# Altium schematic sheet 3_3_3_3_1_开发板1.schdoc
size 762 x 509 mm; Device: Sheet-Symbol; Symbol: Sheet-Symbol; Name: Sheet-Symbol; @Page No: 2; @Page Count: 2; @Schematic Name: 1_1_1_1_3_电源模块; @Project Name: Altium_Altium_Altium_新硬件设计比赛pcb1234567_2025-09-07_2025-09-08_2025-09-08; @Board Name: 1_1_1_1_3_电源模块; @Update Date: 2026-05-23; @Create Time: 14:33:01; @Update Time: 14:01:25; @Page Name: 3_3_3_3_1_开发板1; @Create Date: 2026-05-21
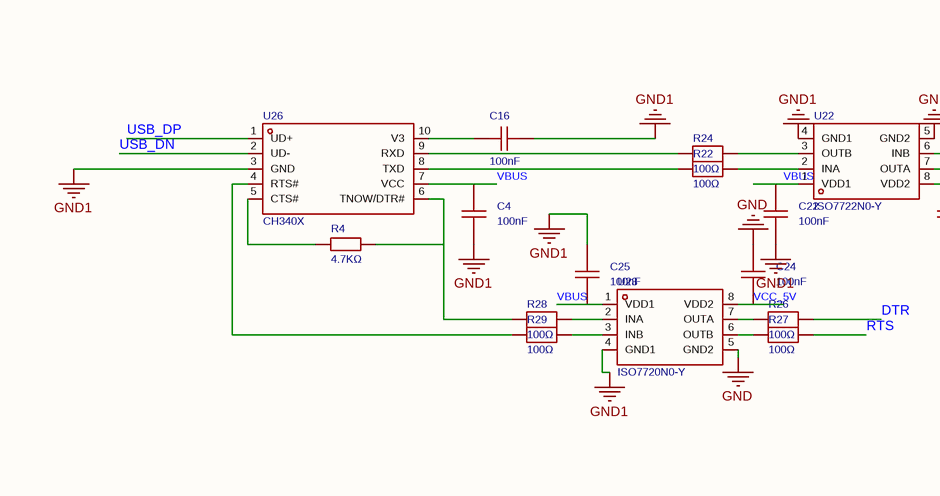
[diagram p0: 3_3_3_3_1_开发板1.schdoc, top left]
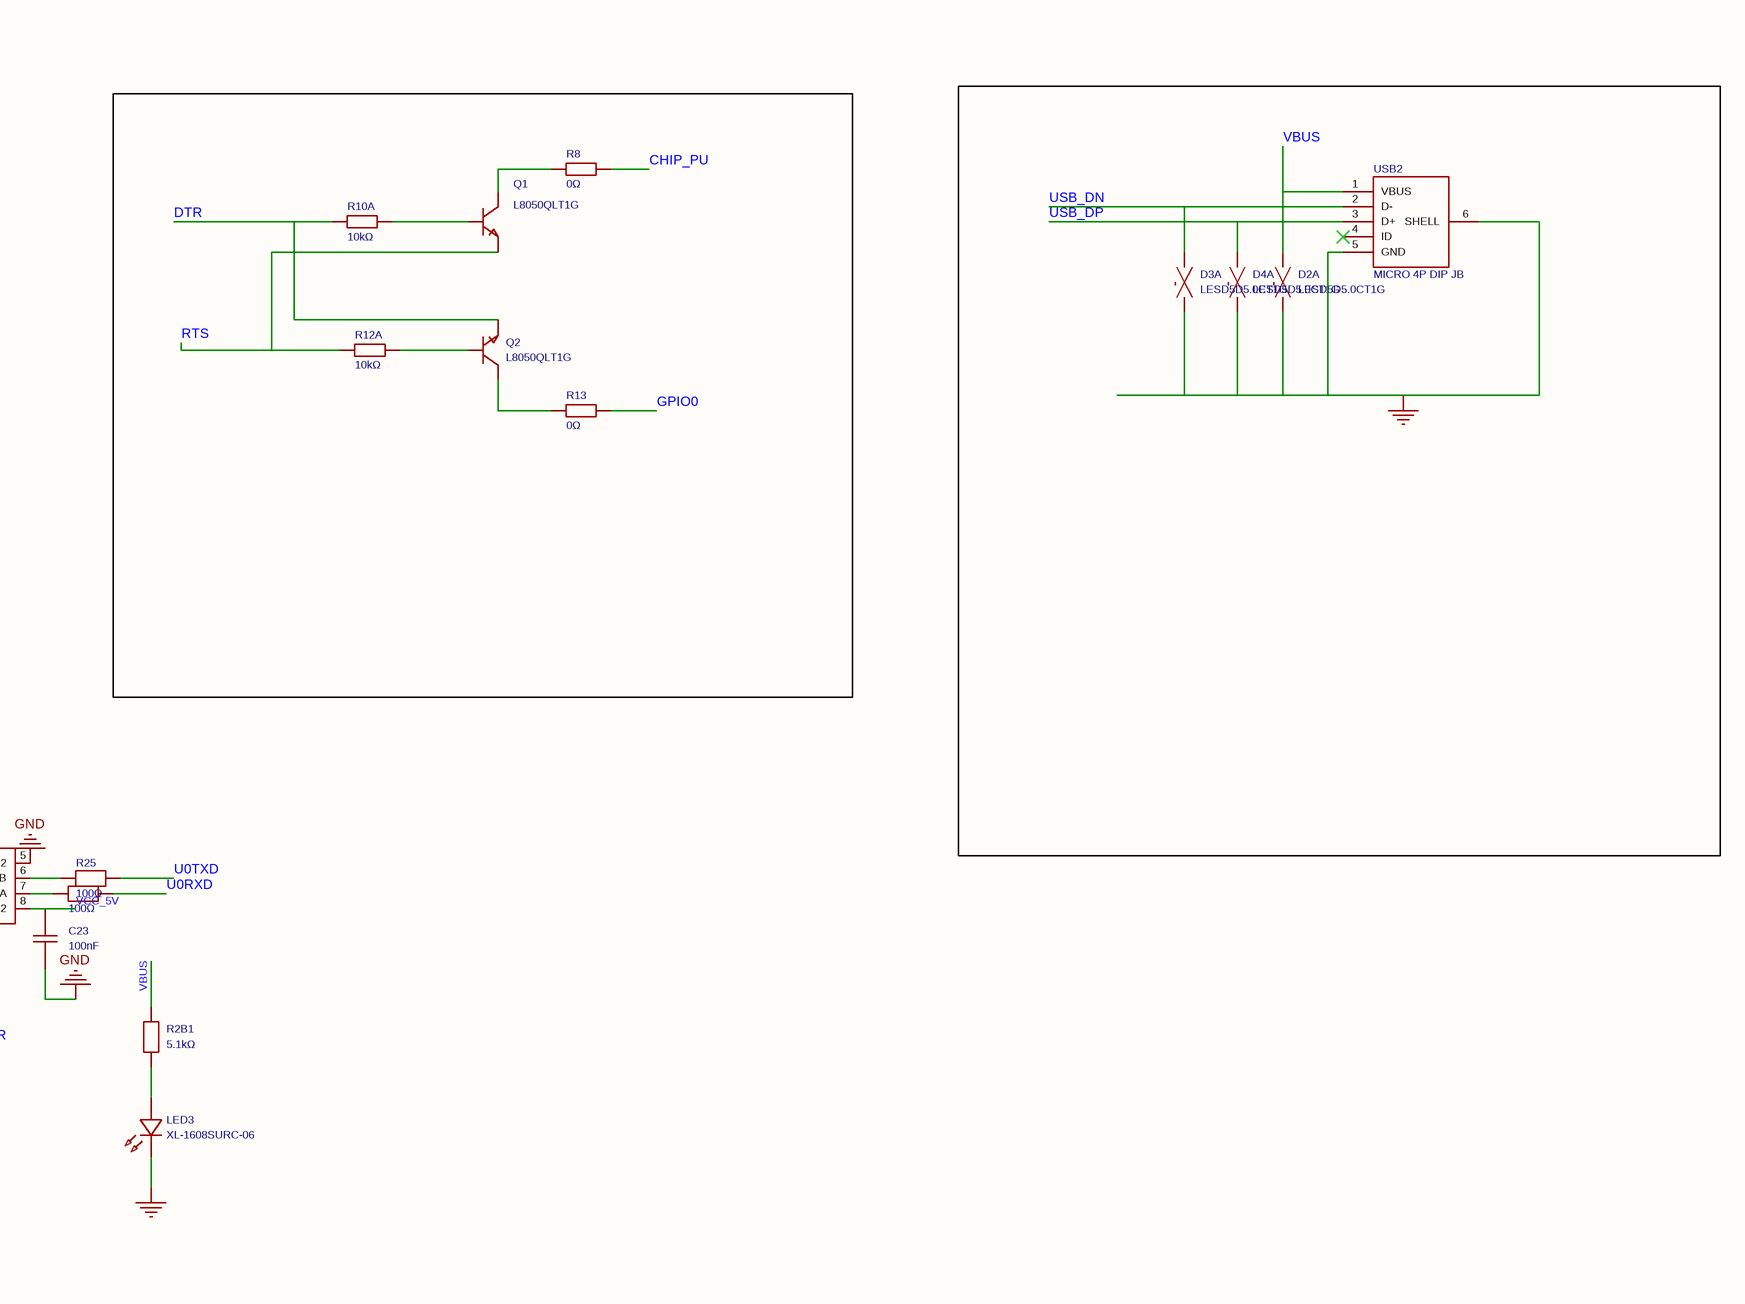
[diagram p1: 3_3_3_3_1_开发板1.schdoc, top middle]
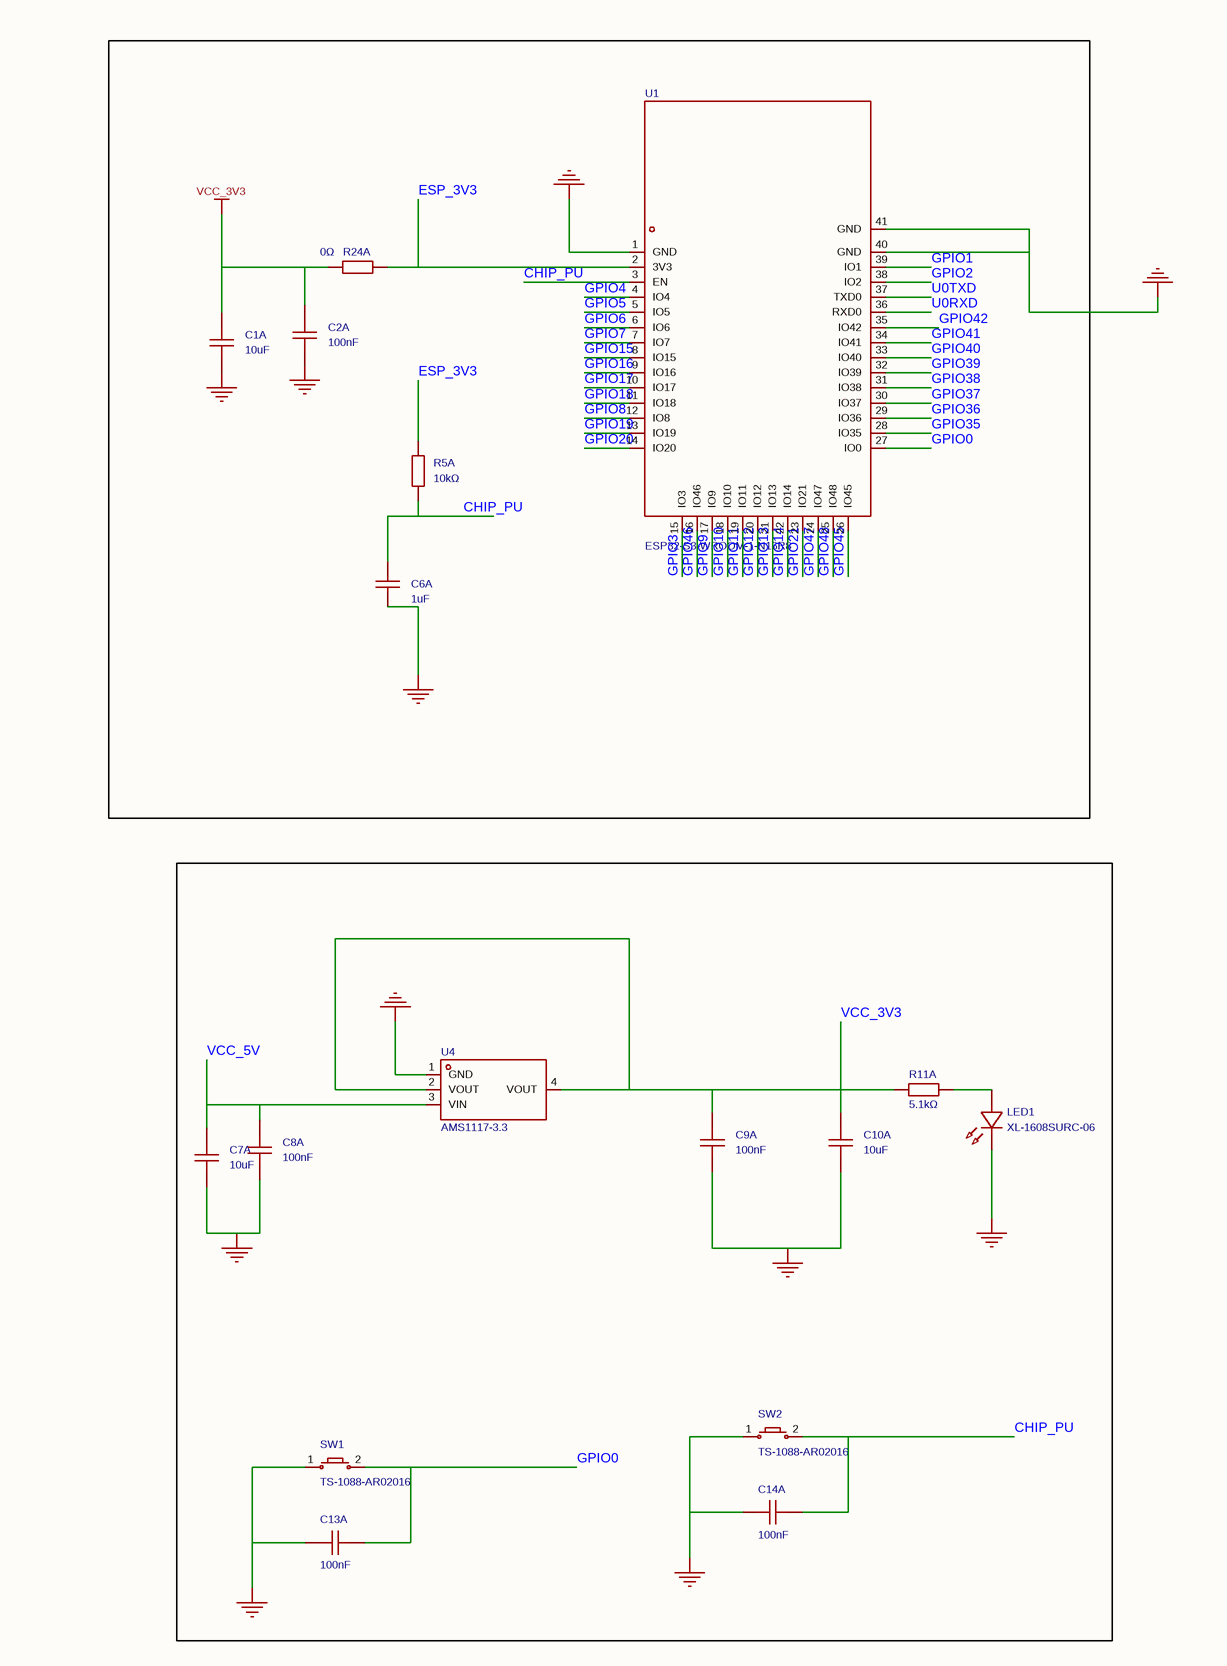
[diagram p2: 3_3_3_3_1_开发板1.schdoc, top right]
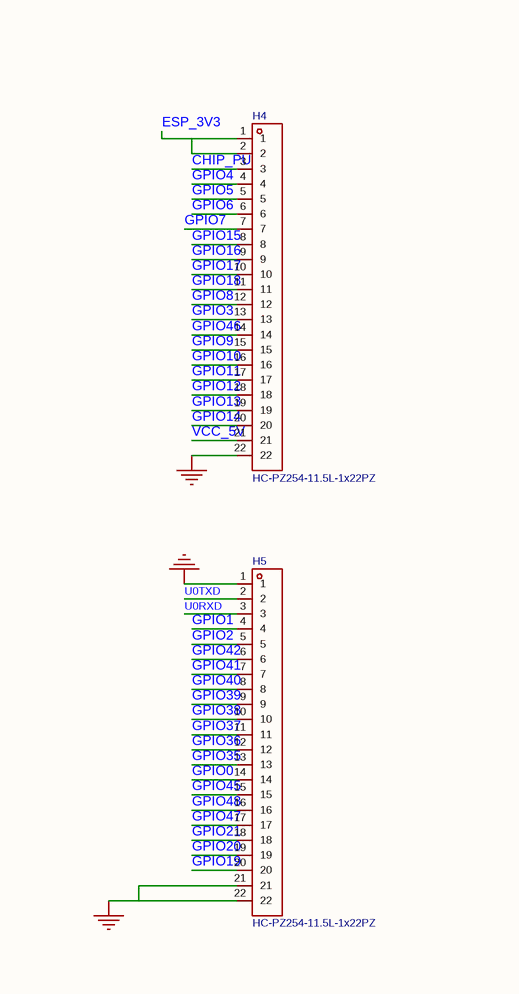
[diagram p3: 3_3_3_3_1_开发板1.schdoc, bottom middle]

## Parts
C1A  10uF  [C0603]
C2A  100nF  [C0603]
C4  100nF  [C0603]
C6A  1uF  [C0603]
C7A  10uF  [C0603]
C8A  100nF  [C0603]
C9A  100nF  [C0603]
C10A  10uF  [C0603]
C13A  100nF  [C0603]
C14A  100nF  [C0603]
C16  100nF  [C0603]
C22  100nF  [C0603]
C23  100nF  [C0603]
C24  100nF  [C0603]
C25  100nF  [C0603]
D2A  LESD5D5.0CT1G  [SOD-523_L1.2-W0.8-LS1.6-BI]
D3A  LESD5D5.0CT1G  [SOD-523_L1.2-W0.8-LS1.6-BI]
D4A  LESD5D5.0CT1G  [SOD-523_L1.2-W0.8-LS1.6-BI]
H4  HC-PZ254-11.5L-1x22PZ  [HDR-TH_22P-P2.54-V-M]
H5  HC-PZ254-11.5L-1x22PZ  [HDR-TH_22P-P2.54-V-M]
LED1  XL-1608SURC-06  [LED0603-RD_RED]
LED3  XL-1608SURC-06  [LED0603-RD_RED]
Q1  L8050QLT1G  [SOT-23-3_L2.9-W1.3-P1.90-LS2.4-BR]
Q2  L8050QLT1G  [SOT-23-3_L2.9-W1.3-P1.90-LS2.4-BR]
R2B1  5.1kΩ  [R0603]
R4  4.7KΩ  [R0603]
R5A  10kΩ  [R0603]
R7A1  100Ω  [R0603]
R8  0Ω  [R0603]
R10A  10kΩ  [R0603]
R11A  5.1kΩ  [R0603]
R12A  10kΩ  [R0603]
R13  0Ω  [R0603]
R22  100Ω  [R0603]
R24  100Ω  [R0603]
R24A  0Ω  [R0603]
R25  100Ω  [R0603]
R26  100Ω  [R0603]
R27  100Ω  [R0603]
R28  100Ω  [R0603]
R29  100Ω  [R0603]
SW1  TS-1088-AR02016  [SW-SMD_L3.9-W3.0-P4.45]
SW2  TS-1088-AR02016  [SW-SMD_L3.9-W3.0-P4.45]
U1  ESP32-S3-WROOM-1-N16R8  [WIRELM-SMD_ESP32-S3-WROOM-1]
U4  AMS1117-3.3  [SOT-223-3_L6.5-W3.4-P2.30-LS7.0-BR]
U22  ISO7722N0-Y  [SOIC-8_L4.9-W3.9-P1.27-LS6.2-BL]
U23  ISO7720N0-Y  [SOIC-8_L4.9-W3.9-P1.27-LS6.2-BL]
U26  CH340X  [MSOP-10_L3.0-W3.0-P0.50-LS5.0-BL]
USB2  MICRO 4P DIP JB  [MICRO-USB-SMD_MICRO-4P-DIP-JB]

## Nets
GND: C1A.1 C2A.1 C6A.1 C7A.1 C8A.1 C9A.1 C10A.1 C13A.1 C14A.1 C23.1 C24.2 H4.22 H5.1 H5.21 H5.22 LED1.1(K) SW1.1 SW2.1 U1.1(GND) U1.40(GND) U1.41(GND) U4.1(GND) U22.5(GND2) U23.5(GND2)
GND1: C4.1 C16.1 C22.1 C25.2 D2A.1 D3A.1 D4A.1 LED3.1(K) U22.4(GND1) U23.4(GND1) U26.3(GND) USB2.5(GND) USB2.6(SHELL)
VCC_3V3: C1A.2 C2A.2 C9A.2 C10A.2 R11A.1 R24A.1 U4.2(VOUT) U4.4(VOUT)
CHIP_PU: C6A.2 C14A.2 H4.3 R5A.1 R8.2 SW2.2 U1.3(EN)
DTR: Q2.2(E) R10A.1 R26.2
ESP_3V3: H4.1 H4.2 R5A.2 R24A.2 U1.2(3V3)
GPIO0: C13A.2 H5.14 R13.2 SW1.2 U1.27(IO0)
GPIO1: H5.4 U1.39(IO1)
GPIO2: H5.5 U1.38(IO2)
GPIO3: H4.13 U1.15(IO3)
GPIO4: H4.4 U1.4(IO4)
GPIO5: H4.5 U1.5(IO5)
GPIO6: H4.6 U1.6(IO6)
GPIO7: H4.7 U1.7(IO7)
GPIO8: H4.12 U1.12(IO8)
GPIO9: H4.15 U1.17(IO9)
GPIO10: H4.16 U1.18(IO10)
GPIO11: H4.17 U1.19(IO11)
GPIO12: H4.18 U1.20(IO12)
GPIO13: H4.19 U1.21(IO13)
GPIO14: H4.20 U1.22(IO14)
GPIO15: H4.8 U1.8(IO15)
GPIO16: H4.9 U1.9(IO16)
GPIO17: H4.10 U1.10(IO17)
GPIO18: H4.11 U1.11(IO18)
GPIO19: H5.20 U1.13(IO19)
GPIO20: H5.19 U1.14(IO20)
GPIO21: H5.18 U1.23(IO21)
GPIO35: H5.13 U1.28(IO35)
GPIO36: H5.12 U1.29(IO36)
GPIO37: H5.11 U1.30(IO37)
GPIO38: H5.10 U1.31(IO38)
GPIO39: H5.9 U1.32(IO39)
GPIO40: H5.8 U1.33(IO40)
GPIO41: H5.7 U1.34(IO41)
GPIO42: H5.6 U1.35(IO42)
GPIO45: H5.15 U1.26(IO45)
GPIO46: H4.14 U1.16(IO46)
GPIO47: H5.17 U1.24(IO47)
GPIO48: H5.16 U1.25(IO48)
RTS: Q1.2(E) R12A.1 R27.2
U0RXD: H5.3 R7A1.2 U1.36(RXD0)
U0TXD: H5.2 R25.2 U1.37(TXD0)
USB_DN: D3A.2 U26.2(UD-) USB2.2(D-)
USB_DP: D4A.2 U26.1(UD+) USB2.3(D+)
VBUS: C4.2 C22.2 C25.1 D2A.2 R2B1.2 U22.1(VDD1) U23.1(VDD1) U26.7(VCC) USB2.1(VBUS)
VCC_5V: C7A.2 C8A.2 C23.2 C24.1 H4.21 U4.3(VIN) U22.8(VDD2) U23.8(VDD2)
NetC16_2: C16.2 U26.10(V3)
NetLED1_2: LED1.2(A) R11A.2
NetLED3_2: LED3.2(A) R2B1.1
NetQ1_1: Q1.1(B) R10A.2
NetQ1_3: Q1.3(C) R8.1
NetQ2_1: Q2.1(B) R12A.2
NetQ2_3: Q2.3(C) R13.1
NetR4_1: R4.1 U26.5(CTS#)
NetR4_2: R4.2 R28.1 U26.6(TNOW/DTR#)
NetR7A1_1: R7A1.1 U22.7(OUTA)
NetR22_1: R22.1 U26.8(TXD)
NetR22_2: R22.2 U22.2(INA)
NetR24_1: R24.1 U26.9(RXD)
NetR24_2: R24.2 U22.3(OUTB)
NetR25_1: R25.1 U22.6(INB)
NetR26_1: R26.1 U23.7(OUTA)
NetR27_1: R27.1 U23.6(OUTB)
NetR28_2: R28.2 U23.2(INA)
NetR29_1: R29.1 U26.4(RTS#)
NetR29_2: R29.2 U23.3(INB)

Not connected (* = marked no-connect by the designer): USB2 4(ID)*

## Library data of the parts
C1A = FCC0603X106M6R3CT: 容值:10uF;精度:±20%;额定电压:6.3V;温度系数:X5R;; Manufacturer: FOJAN(富捷); Add into BOM: yes; 3D Model: ac125912035d415993ca9572d50418b1; 3D Model Transform: 62.992,31.496,0,0,0,0,0,0,0; Tolerance: ±20%; Voltage Rating: 6.3V; Temperature Coefficient: X5R; ModelName: C0603_L1.6-W0.8-H0.8
C2A C4 C8A C9A C13A C14A C16 C22-C25 = FCC0603B104K500CT: 容值:100nF;精度:±10%;额定电压:50V;温度系数:X7R;; Manufacturer: FOJAN(富捷); Add into BOM: yes; 3D Model: ac125912035d415993ca9572d50418b1; 3D Model Transform: 62.992,31.496,0,0,0,0,0,0,0; Tolerance: ±10%; Voltage Rating: 50V; Temperature Coefficient: X7R; ModelName: C0603_L1.6-W0.8-H0.8
C6A = CL10B105KA8NNNC: 容值:1uF;精度:±10%;额定电压:25V;温度系数:X7R;; Manufacturer: SAMSUNG(三星); Add into BOM: yes; 3D Model: ac125912035d415993ca9572d50418b1; 3D Model Transform: 62.992,31.496,0,0,0,0,0,0,0; Tolerance: ±10%; Voltage Rating: 25V; Temperature Coefficient: X7R; ModelName: C0603_L1.6-W0.8-H0.8
C7A C10A = CL10A106KP8NNNC: 容值:10uF;精度:±10%;额定电压:10V;温度系数:X5R;; Manufacturer: SAMSUNG(三星); Add into BOM: yes; 3D Model: ac125912035d415993ca9572d50418b1; 3D Model Transform: 62.992,31.496,0,0,0,0,0,0,0; Tolerance: ±10%; Temperature Coefficient: X5R; Voltage Rating: 10V; ModelName: C0603_L1.6-W0.8-H0.8
D2A D3A D4A = LESD5D5.0CT1G: Manufacturer: LRC(乐山无线电); Add into BOM: yes; Polarity: 双向; Reverse Stand-Off Voltage (Vrwm): 5V; Clamping Voltage: 18.6V; Peak Pulse Current (Ipp): 9.4A@8/20us; Peak Pulse Power Dissipation (Ppp): 150W@8/20us; Voltage - Breakdown: 7.8V; Reverse Leakage Current (Ir): 1uA; level of protection: IEC 61000-4-4；IEC 61000-4-2; Type: ESD; Junction Capacitance: 15pF; ModelId: bfbc20aaa9964d25bc07bd43d1c87046
H4 H5 = HC-PZ254-11.5L-1x22PZ: 插针结构:1x22P;间距:2.54mm;行距:-;圆针/方针:方针;安装方式:直插;排数:单排;总PIN位数:22P;额定电流:3A;额定电压:-;配合针长度:6mm;塑高:2.5mm;端接针长度:3mm;触头材质:黄铜;触头镀层:金;工作温度:-40℃~+105℃;颜色:黑色;; Manufacturer: HC(虹成电子); AddInBom: yes; ModelId: 875f4c094945453e8148e92095c9b8a7; ModelName: HDR-TH_22P-P2.54-M-LI-1X22P; ModelTransform: 2199.99552,98.425,0,0,0,0,0,0,-118.11; Pin Structure: 1x22P; Pitch: 2.54mm; Circluar Pins/Square Pins: 方针; Current Rating: 3A
LED1 LED3 = XL-1608SURC-06: 灯头类型:1.6mmx0.8mm方形灯头;发光颜色:红色;正向压降(Vf):2.3V;功率:50mW;正向电流:20mA;波长:620nm~630nm;二极管配置:独立二极管;透镜颜色:无色透明透镜;色温:-;发光强度:225mcd;发光角度:120°;载带方式:正贴;工作温度:-40℃~+85℃;; Manufacturer: XINGLIGHT(成兴光); Add into BOM: yes; Illumination Color: 红色; Voltage - Forward(Vf): 2.3V; Power(Watts): 50mW; Forward Current: 20mA; Peak Wavelength: 625nm; Diode Configuration: 独立二极管; Lens Color: 无色透明透镜; Luminous Intensity: 225mcd; Viewing Angle: 120°; 3D Model: 74041d3a270d435c8600a9ab9b7641c0; 3D Model Transform: 63.7794,31.496,0,0,0,0,0,-0.002,0
Q1 Q2 = L8050QLT1G: Manufacturer: LRC(乐山无线电); Add into BOM: yes; type: NPN; Current - Collector(Ic): 800mA; Collector - Emitter Voltage VCEO: 25V; Pd - Power Dissipation: 225mW; DC Current Gain: 100@100mA,1V; Current - Collector Cutoff: 150nA; Vce Saturation(VCE(sat)): 500mV
R2B1 = RCA035K1JLF: 阻值:5.1kΩ;精度:±5%;功率:100mW;; Manufacturer: HKR(香港电阻); Add into BOM: yes; 3D Model: fc143cca1e79419f9cd78b61e9279f08; 3D Model Transform: 31.8897,63.7794,0,90,0,0,0,0,0; Tolerance: ±5%; Power(Watts): 100mW
R4 = Res_0603: Symbol: 电阻; ConvertToPcb: yes; ModelId: fc143cca1e79419f9cd78b61e9279f08; ModelTransform: 31.8897,63.7794,0,90,0,0,0,0,0
R5A R10A R12A = 0603WAF1002T5E: 电阻类型:厚膜电阻;阻值:10kΩ;精度:±1%;功率:100mW;工作电压:75V;温度系数:±100ppm/℃;; Manufacturer: UNI-ROYAL(厚声); Symbol: Res_0603; Convert to PCB: yes; ModelId: fc143cca1e79419f9cd78b61e9279f08; ModelTransform: 31.8897,63.7794,0,90,0,0,0,0,0; Tolerance: ±1%; Power(Watts): 100mW; Voltage-Supply(Max): 75V
R7A1 R22 R24-R29 = FRC0603F1000TS: 电阻类型:厚膜电阻;阻值:100Ω;精度:±1%;功率:100mW;工作电压:75V;温度系数:±100ppm/℃;; Manufacturer: FOJAN(富捷); Add into BOM: yes; 3D Model: fc143cca1e79419f9cd78b61e9279f08; 3D Model Transform: 31.8897,63.7794,0,90,0,0,0,0,0; Tolerance: ±1%; Power(Watts): 100mW; Voltage-Supply(Max): 75V
R8 R13 R24A = 0603WAF0000T5E: 电阻类型:厚膜电阻;阻值:0Ω;精度:±1%;功率:100mW;工作电压:75V;温度系数:-;; Manufacturer: UNI-ROYAL(厚声); Symbol: Res_0603; Convert to PCB: yes; ModelId: fc143cca1e79419f9cd78b61e9279f08; ModelTransform: 31.8897,63.7794,0,90,0,0,0,0,0; Tolerance: ±1%; Power(Watts): 100mW; Voltage-Supply(Max): 75V
R11A = 0603WAF5101T5E: 电阻类型:厚膜电阻;阻值:5.1kΩ;精度:±1%;功率:100mW;工作电压:75V;温度系数:±100ppm/℃;; Manufacturer: UNI-ROYAL(厚声); Symbol: Res_0603; Convert to PCB: yes; ModelId: fc143cca1e79419f9cd78b61e9279f08; ModelTransform: 31.8897,63.7794,0,90,0,0,0,0,0; Tolerance: ±1%; Power(Watts): 100mW; Voltage-Supply(Max): 75V
SW1 SW2 = TS-1088-AR02016: 电路结构:单刀单掷;按钮形状:圆形按钮;作用力:1.6N;安装方式:立贴;开关长度:4mm;开关宽度:3mm;开关高度:2mm;带支架:不带支架;触点电流:50mA;额定电压:12V;工作寿命:10万次;; Manufacturer: XUNPU(讯普); Symbol: Key_SMD_3x4x2; Convert to PCB: yes; ModelId: b26698b69f274ffabef8a26c7d0e5dd1; ModelName: SW-SMD_L3.9-W2.9-H2.0-LS4.8; ModelTransform: 188.976,114.174,0,0,0,0,0,0,0; Circuit: 单刀单掷; Actuator Style: 圆形按钮; Operating Force: 1.6N; Switch Height: 2mm; with Bracket: 不带支架; Contact Current: 50mA; Voltage Rating: 12V; Actuator/Cap Color: 黑色; Life: 10万次
U1 = ESP32-S3-WROOM-1-N16R8: Manufacturer: ESPRESSIF(乐鑫); Add into BOM: yes; ModelId: 481f5bdfc076422c9bb3c23c3ada9c17
U4 = AMS1117-3.3_C6186: 输出类型:固定;工作电压:15V;输出电压:3.3V;输出电流:1A;电源纹波抑制比(PSRR):72dB@(120Hz);输出极性:正极;; Manufacturer: AMS; Add into BOM: yes; Output Type: 固定; Voltage - Supply: 15V; Output Voltage: 3.3V; Output Current: 1A; Voltage Dropout: 1.1V@(800mA); standby current: 5mA; Noise: 0.003%Vout; 3D Model: 925194bf9823436183a3e0b978a8d076; 3D Model Transform: 279.89794,255.905,0,180,0,0,-3.9385,-0.0005,0; Output Configuration: 正极; Number of Outputs: 1; ModelName: SOT-223-4P_L6.5-W3.5-H1.6-LS7.0-P2.30
U22 = ISO7722N0-Y: 两通道数字隔离器,电容隔离，SOP8封装; Manufacturer: YLPTEC(易川); AddInBom: yes; ModelId: 23a59470b1e946e0afe388c2a9d3f488; ModelTransform: 192.913,236.22,0,0,0,0,0,0,0; Number of Forward Channels: 1; Data Rate(Max): 150Mbps; Default Output: 低电平; Isolation Voltage(Vrms): 3750; CMTI(kV/us): 200kV/us; Voltage - Supply(VCCA): 2.5V~5.5V
U23 = ISO7720N0-Y: 两通道数字隔离器,电容隔离，SOP8封装; Manufacturer: YLPTEC(易川); Symbol: ISO7720N1-Y; AddInBom: yes; ModelId: 23a59470b1e946e0afe388c2a9d3f488; ModelTransform: 192.913,236.22,0,0,0,0,0,0,0; Number of Forward Channels: 2; Number of Reverse Channels: 0; Data Rate(Max): 150Mbps; Default Output: 低电平; Isolation Voltage(Vrms): 3750; CMTI(kV/us): 200kV/us; Voltage - Supply(VCCA): 2.5V~5.5V
U26 = CH340X: 应用功能:USB转串口；USB转并口;USB协议版本:USB 2.0;通道数:-;数据速率:2Mbps;; Manufacturer: WCH(南京沁恒); AddInBom: yes; ModelId: b42a31f9e1fa4643bc7ea573b9bba7ed; ModelName: MSOP-10_L3.0-W3.0-H1.1-LS5.0-P0.50; ModelTransform: 118.11,196.85,0,0,0,0,0,0,0; USB Protocol: USB 2.0; Voltage - Supply: 3.3V；5V; Data Rate: 2Mbps
USB2 = MICRO 4P DIP JB: Manufacturer: SHOU HAN(首韩); Add into BOM: yes; Connector Type: Micro-B; Protocol Standard: USB 2.0; Gender: 母; Number of Ports: 1; Current Rating-Power: 1A; Voltage Rating: 30V; Connect-Disconnect Life: 3千次; Detection color: 黑色; ModelId: eed8ec7ddbe54e01a232e82f55e3a767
